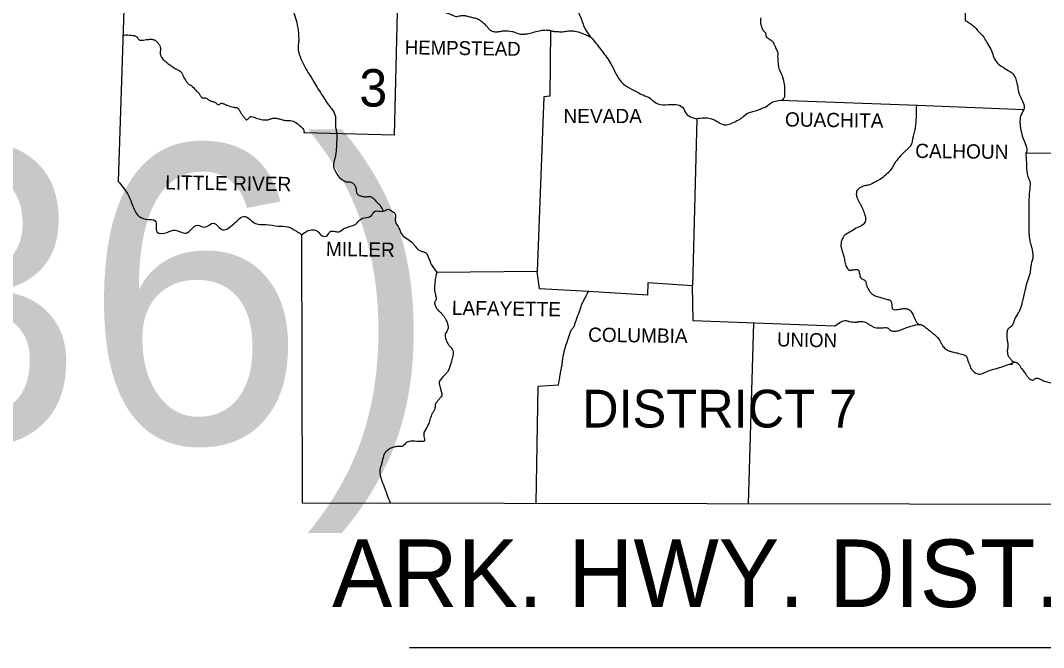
# Model space of a CAD drawing. Extents: x 0 to 3171, y 0 to 2059.
# Drawn here: x 2503.4 to 2812.1, y 1309.2 to 1498.5 of the extents above; entities that cross this region are included whole.
import ezdxf

# ---------------------------------------------------------------- set-up
doc = ezdxf.new("R2010")
doc.units = 0
doc.layers.add('Default', color=7, linetype='Continuous')
doc.layers.add('Level 1', color=7, linetype='Continuous')

msp = doc.modelspace()

# ---------------------------------------------------------------- linework, layer by layer
at = {"layer": 'Default'}
msp.add_line((2620.8, 1309.22), (2939.39, 1309.22), dxfattribs=at)
at = {"layer": 'Level 1'}
for points in [[(2521.17, 1887.43), (2541.87, 1721.24), (2532.87, 1449.94)], [(2602.57, 1557.14), (2602.57, 1543.84), (2604.77, 1543.44), (2604.57, 1531.04), (2617.77, 1530.04), (2616.17, 1463.94), (2588.97, 1464.64)], [(2803.21, 1511.94), (2788.57, 1511.04), (2788.47, 1498.54)], [(2663.37, 1495.49), (2663.17, 1475.64), (2661.37, 1475.44), (2659.37, 1422.75)], [(2732.67, 1474.44), (2774.07, 1472.94), (2806.18, 1471.69)], [(2707.47, 1468.84), (2706.17, 1418.45), (2692.67, 1419.35), (2692.57, 1415.65), (2674.78, 1416.69)], [(2806.77, 1458.44), (2851.97, 1458.54)], [(2588.17, 1433.84), (2588.37, 1352.95), (2954.87, 1352.35)], [(2659.37, 1422.75), (2629.07, 1422.45)], [(2674.78, 1416.69), (2660.07, 1417.55), (2659.37, 1422.75)], [(2749.07, 1406.25), (2706.37, 1407.85), (2706.17, 1418.45)], [(2724.58, 1407.16), (2722.99, 1352.73)], [(2665.77, 1388.45), (2659.57, 1388.05), (2658.89, 1352.83)]]:
    msp.add_lwpolyline(points, dxfattribs=at)
for points in [[(2658.07, 1536.64), (2659.67, 1535.64), (2661.57, 1534.74), (2662.57, 1533.24), (2662.97, 1530.94), (2663.67, 1528.44), (2663.87, 1525.84), (2663.27, 1524.44), (2664.07, 1521.24), (2664.37, 1519.04), (2664.67, 1516.44), (2665.47, 1512.94), (2666.77, 1510.54), (2667.97, 1507.64), (2669.97, 1504.54), (2671.67, 1501.14), (2672.47, 1499.34), (2673.97, 1495.64), (2675.87, 1493.14), (2678.87, 1489.34), (2681.57, 1485.44), (2683.07, 1482.54), (2685.37, 1479.34), (2687.97, 1477.74), (2691.27, 1476.04), (2693.37, 1475.04), (2695.77, 1473.34), (2698.87, 1473.14), (2701.17, 1473.14), (2703.27, 1472.24), (2704.27, 1470.44), (2706.07, 1469.24), (2707.47, 1468.84)], [(2581.07, 1531.04), (2581.57, 1528.04), (2581.76, 1527.38), (2582.01, 1526.74), (2582.27, 1526.1), (2582.47, 1525.44), (2582.53, 1524.95), (2582.53, 1524.44), (2582.53, 1523.94), (2582.57, 1523.44), (2582.77, 1522.69), (2583.04, 1521.95), (2583.31, 1521.21), (2583.47, 1520.44), (2583.47, 1519.34), (2583.53, 1518.79), (2583.62, 1518.24), (2583.72, 1517.69), (2583.77, 1517.14), (2583.71, 1516.84), (2583.57, 1516.54), (2583.43, 1516.24), (2583.37, 1515.94), (2583.46, 1515.35), (2583.63, 1514.75), (2583.8, 1514.15), (2583.87, 1513.54), (2583.77, 1511.74), (2583.77, 1510.24), (2583.87, 1507.74), (2584.01, 1507.18), (2584.23, 1506.63), (2584.48, 1506.1), (2584.67, 1505.54), (2585.47, 1502.24), (2585.97, 1500.54), (2586.77, 1497.94), (2587.27, 1494.74), (2587.37, 1492.34), (2587.34, 1491.79), (2587.26, 1491.24), (2587.19, 1490.69), (2587.17, 1490.14), (2587.77, 1487.64), (2588.87, 1485.14), (2590.27, 1482.74), (2591.97, 1480.04), (2593.17, 1477.94), (2594.67, 1475.64), (2595.87, 1473.74), (2596.3, 1473.13), (2596.76, 1472.55), (2597.23, 1471.96), (2597.67, 1471.34), (2598.47, 1469.34), (2598.52, 1468.64), (2598.49, 1467.94), (2598.45, 1467.24), (2598.47, 1466.54), (2598.57, 1465.89), (2598.7, 1465.25), (2598.82, 1464.6), (2598.87, 1463.94), (2598.77, 1461.04), (2598.57, 1458.44), (2598.43, 1457.54), (2598.21, 1456.64), (2598, 1455.74), (2597.87, 1454.84), (2598.37, 1453.14), (2600.27, 1450.64), (2601.47, 1449.94), (2601.98, 1449.82), (2602.53, 1449.8), (2603.07, 1449.75), (2603.57, 1449.54), (2604.16, 1448.9), (2604.57, 1448.14), (2604.72, 1447.62), (2604.76, 1447.05), (2604.86, 1446.5), (2604.98, 1446.26), (2605.17, 1446.04), (2606.19, 1445.55), (2607.27, 1445.34), (2607.56, 1445.31), (2607.87, 1445.33), (2608.49, 1445.39), (2609.08, 1445.39), (2609.57, 1445.14), (2610.67, 1443.94), (2612.17, 1442.34), (2612.9, 1440.94)], [(2617.13, 1503.54), (2621.37, 1503.14), (2624.87, 1502.74), (2626.23, 1502.64), (2626.9, 1502.57), (2627.24, 1502.51), (2627.57, 1502.44), (2628.29, 1502.23), (2628.98, 1501.98), (2630.37, 1501.44), (2632.87, 1500.54), (2633.27, 1500.38), (2633.67, 1500.19), (2634.06, 1500), (2634.47, 1499.84), (2635.13, 1499.77), (2635.81, 1499.89), (2636.5, 1500.03), (2637.17, 1500.04), (2638.32, 1499.82), (2639.47, 1499.54), (2640.8, 1499.19), (2641.45, 1498.96), (2641.76, 1498.81), (2642.07, 1498.64), (2643.07, 1497.84), (2643.97, 1496.94), (2644.26, 1496.62), (2644.52, 1496.28), (2645.17, 1495.64), (2645.73, 1495.34), (2646.31, 1495.19), (2647.47, 1495.14), (2647.94, 1495.2), (2648.42, 1495.3), (2648.89, 1495.4), (2649.37, 1495.44), (2651.67, 1495.24), (2652.33, 1495.07), (2652.97, 1494.82), (2653.61, 1494.59), (2654.27, 1494.44), (2654.79, 1494.4), (2655.32, 1494.41), (2656.37, 1494.54), (2658.07, 1494.94), (2660.07, 1495.44), (2661.32, 1495.64), (2661.95, 1495.66), (2662.57, 1495.64), (2663.05, 1495.57), (2663.52, 1495.45), (2663.99, 1495.33), (2664.47, 1495.24), (2665.72, 1495.16), (2666.97, 1495.14), (2667.7, 1495.2), (2668.42, 1495.32), (2669.15, 1495.42), (2669.51, 1495.45), (2669.87, 1495.44), (2670.61, 1495.35), (2672.79, 1494.72), (2674.21, 1494.11), (2675.6, 1493.49)], [(2726.77, 1499.34), (2726.66, 1498.4), (2726.69, 1497.92), (2726.77, 1497.44), (2726.89, 1496.98), (2727.05, 1496.52), (2727.24, 1496.08), (2727.47, 1495.64), (2727.63, 1495.43), (2727.82, 1495.23), (2728.01, 1495.05), (2728.17, 1494.84), (2728.27, 1494.53), (2728.29, 1494.17), (2728.32, 1493.83), (2728.37, 1493.67), (2728.47, 1493.54), (2728.68, 1493.37), (2728.91, 1493.23), (2729.15, 1493.1), (2729.37, 1492.94), (2729.54, 1492.81), (2729.73, 1492.67), (2730.09, 1492.4), (2730.41, 1492.1), (2730.55, 1491.93), (2730.67, 1491.74), (2730.87, 1491.32), (2731.04, 1490.9), (2731.2, 1490.47), (2731.37, 1490.04), (2731.64, 1489.5), (2731.77, 1489.23), (2731.82, 1489.09), (2731.87, 1488.94), (2731.92, 1488.6), (2731.91, 1488.25), (2731.88, 1487.89), (2731.87, 1487.54), (2731.92, 1486.84), (2731.97, 1486.14), (2732.05, 1485.29), (2732.1, 1484.87), (2732.17, 1484.44), (2732.4, 1483.67), (2732.74, 1482.93), (2733.09, 1482.2), (2733.37, 1481.44), (2733.67, 1480.24), (2733.87, 1479.24), (2733.97, 1477.54), (2733.99, 1477.04), (2734, 1476.54), (2733.99, 1476.04), (2733.98, 1475.79), (2733.97, 1475.54), (2733.88, 1475.26), (2733.69, 1474.95), (2733.15, 1474.43)], [(2788.47, 1498.54), (2790.77, 1497.04), (2792.67, 1495.04), (2794.07, 1493.54), (2794.97, 1491.84), (2796.17, 1489.84), (2797.87, 1486.04), (2799.37, 1484.74), (2801.47, 1483.44), (2802.77, 1482.54), (2804.07, 1479.64), (2804.67, 1476.74), (2805.77, 1474.14), (2806.27, 1472.14), (2805.37, 1470.14), (2805.17, 1466.14), (2805.77, 1463.44), (2806.57, 1461.44), (2807.07, 1459.14), (2806.77, 1458.44)], [(2534.33, 1494.08), (2535.34, 1494.18), (2536.38, 1494.15), (2537.35, 1494.04), (2538.17, 1493.84), (2538.53, 1493.56), (2538.87, 1493.11), (2539.23, 1492.7), (2539.67, 1492.54), (2540.57, 1492.64), (2542.17, 1492.84), (2542.54, 1492.88), (2542.92, 1492.88), (2543.3, 1492.83), (2543.67, 1492.74), (2543.99, 1492.59), (2544.27, 1492.38), (2544.53, 1492.13), (2544.77, 1491.84), (2545.07, 1491.46), (2545.34, 1491.08), (2545.54, 1490.68), (2545.67, 1490.24), (2545.69, 1489.87), (2545.64, 1489.49), (2545.58, 1489.12), (2545.57, 1488.74), (2545.67, 1488.14), (2545.79, 1487.78), (2545.94, 1487.44), (2546.37, 1486.84), (2547.57, 1485.84), (2548.87, 1484.84), (2550.07, 1484.04), (2550.33, 1483.89), (2550.61, 1483.75), (2551.18, 1483.49), (2551.7, 1483.18), (2552.07, 1482.74), (2552.27, 1482.34), (2553.07, 1480.74), (2553.51, 1480.06), (2553.78, 1479.74), (2554.07, 1479.44), (2554.36, 1479.22), (2554.68, 1479.05), (2554.99, 1478.87), (2555.27, 1478.64), (2556.57, 1477.24), (2557.17, 1476.64), (2557.43, 1476.31), (2557.65, 1475.93), (2557.88, 1475.57), (2558.02, 1475.4), (2558.17, 1475.24), (2558.42, 1475.15), (2558.71, 1475.16), (2559, 1475.19), (2559.27, 1475.14), (2559.65, 1474.93), (2560.01, 1474.69), (2560.38, 1474.44), (2560.77, 1474.24), (2561.04, 1474.16), (2561.32, 1474.09), (2561.6, 1474.02), (2561.87, 1473.94), (2562.18, 1473.77), (2562.46, 1473.54), (2562.75, 1473.31), (2563.07, 1473.14), (2563.37, 1473.17), (2563.67, 1473.35), (2563.97, 1473.52), (2564.27, 1473.54), (2564.65, 1473.4), (2565.02, 1473.24), (2565.39, 1473.08), (2565.77, 1472.94), (2567.77, 1472.34), (2568.05, 1472.3), (2568.33, 1472.29), (2568.75, 1472.22), (2568.81, 1472.18), (2568.87, 1472.14), (2569.29, 1471.73), (2569.59, 1471.25), (2569.86, 1470.74), (2570.01, 1470.48), (2570.17, 1470.24), (2570.79, 1469.42), (2571.11, 1469.02), (2571.47, 1468.64), (2571.64, 1468.56), (2571.83, 1468.62), (2572.22, 1468.97), (2572.64, 1469.39), (2572.85, 1469.52), (2573.07, 1469.54), (2573.81, 1469.35), (2574.55, 1469.08), (2575.31, 1468.81), (2576.07, 1468.64), (2577.02, 1468.55), (2577.97, 1468.54), (2578.4, 1468.64), (2578.82, 1468.8), (2579.24, 1468.96), (2579.67, 1469.04), (2580.97, 1468.94), (2581.57, 1468.81), (2582.17, 1468.64), (2582.77, 1468.47), (2583.37, 1468.34), (2583.74, 1468.32), (2584.12, 1468.34), (2584.5, 1468.37), (2584.87, 1468.34), (2586.47, 1467.74), (2587.97, 1466.54), (2588.97, 1465.24), (2588.97, 1464.64)], [(2728.17, 1472.34), (2730.77, 1474.04), (2732.67, 1474.44)], [(2773.73, 1472.96), (2773.67, 1469.85), (2773.6, 1468.3), (2773.54, 1467.52), (2773.47, 1466.74), (2773.17, 1465.19), (2772.77, 1463.64), (2772.5, 1462.23), (2772.33, 1461.52), (2772.22, 1461.18), (2772.15, 1461.01), (2772.07, 1460.84), (2771.77, 1460.38), (2771.39, 1459.99), (2770.57, 1459.24), (2769.77, 1458.45), (2768.97, 1457.64), (2767.47, 1455.84), (2767.12, 1455.31), (2766.82, 1454.74), (2766.52, 1454.18), (2766.17, 1453.64), (2764.87, 1452.24), (2763.17, 1450.84), (2761.47, 1449.84), (2759.57, 1448.94), (2759.06, 1448.78), (2758.53, 1448.68), (2758, 1448.59), (2757.47, 1448.44), (2756.64, 1448.02), (2756.28, 1447.72), (2756.12, 1447.54), (2755.97, 1447.34), (2755.7, 1446.76), (2755.62, 1446.14), (2755.87, 1444.94), (2756.28, 1444.09), (2756.72, 1443.25), (2757.17, 1442.41), (2757.57, 1441.54), (2758.17, 1439.94), (2758.3, 1439.48), (2758.39, 1439), (2758.41, 1438.52), (2758.37, 1438.04), (2757.67, 1436.94), (2756.07, 1436.04), (2754.17, 1434.94), (2752.47, 1433.94), (2752.07, 1433.62), (2751.74, 1433.21), (2751.48, 1432.75), (2751.27, 1432.24), (2751, 1431.09), (2751.07, 1429.95), (2751.25, 1429.27), (2751.47, 1428.6), (2751.68, 1427.92), (2751.87, 1427.25), (2752.02, 1426.45), (2752.17, 1425.65), (2752.55, 1424.23), (2752.91, 1423.61), (2753.16, 1423.35), (2753.3, 1423.24), (2753.47, 1423.15), (2753.72, 1423.09), (2753.97, 1423.13), (2754.22, 1423.2), (2754.47, 1423.25), (2754.69, 1423.26), (2754.92, 1423.29), (2755.37, 1423.36), (2755.82, 1423.34), (2756.05, 1423.27), (2756.16, 1423.22), (2756.27, 1423.15), (2756.42, 1422.91), (2756.47, 1422.65), (2756.57, 1422.15), (2756.97, 1420.85), (2757.27, 1420.51), (2757.71, 1420.29), (2758.17, 1420.07), (2758.47, 1419.75), (2758.54, 1419.5), (2758.57, 1419.25), (2758.61, 1418.99), (2758.67, 1418.75), (2759.05, 1417.77), (2759.57, 1416.85), (2759.89, 1416.44), (2760.24, 1416.08), (2761.07, 1415.55), (2762.17, 1415.15), (2764.47, 1414.45), (2765.67, 1414.15), (2765.84, 1414.07), (2766.15, 1413.58), (2766.31, 1412.61), (2766.47, 1411.69), (2766.66, 1411.38), (2766.97, 1411.25), (2767.77, 1411.26), (2768.57, 1411.35), (2769.77, 1411.55), (2770.78, 1411.5), (2771.28, 1411.33), (2771.53, 1411.2), (2771.77, 1411.05), (2772.31, 1410.48), (2772.67, 1409.85), (2772.91, 1409.35), (2773.12, 1408.85), (2773.33, 1408.34), (2773.57, 1407.85), (2774.1, 1407.08), (2774.38, 1406.78)], [(2728.17, 1472.34), (2727.45, 1472.05), (2726.17, 1471.54), (2724.67, 1471.04), (2723.27, 1470.64), (2721.47, 1469.44), (2720.07, 1468.44), (2718.17, 1467.54), (2716.37, 1466.94), (2714.17, 1467.64), (2712.97, 1468.34), (2711.67, 1468.84), (2707.47, 1468.84)], [(2806.77, 1458.44), (2806.85, 1456.89), (2806.94, 1455.34), (2807.17, 1452.24), (2807.35, 1451.48), (2807.65, 1450.74), (2807.95, 1450), (2808.04, 1449.63), (2808.07, 1449.24), (2808.02, 1448.45), (2807.93, 1447.65), (2807.83, 1446.85), (2807.77, 1446.04), (2807.67, 1442.94), (2807.67, 1440.14), (2807.67, 1437.44), (2807.67, 1434.64), (2807.87, 1432.64), (2808.02, 1431.91), (2808.21, 1431.19), (2808.4, 1430.47), (2808.57, 1429.75), (2808.81, 1428.39), (2808.88, 1427.72), (2808.87, 1427.05), (2808.77, 1426.39), (2808.6, 1425.74), (2808.41, 1425.1), (2808.27, 1424.45), (2808.2, 1423.85), (2808.14, 1423.24), (2808.08, 1422.64), (2807.97, 1422.05), (2807.79, 1421.44), (2807.58, 1420.84), (2807.36, 1420.25), (2807.17, 1419.65), (2806.47, 1416.95), (2805.67, 1413.45), (2805.36, 1412.28), (2805.18, 1411.71), (2804.97, 1411.15), (2804.67, 1410.52), (2804.3, 1409.93), (2803.92, 1409.34), (2803.57, 1408.75), (2803.33, 1408.21), (2803.11, 1407.65), (2802.9, 1407.09), (2802.67, 1406.55), (2802.36, 1406.17), (2801.94, 1405.87), (2801.54, 1405.56), (2801.38, 1405.37), (2801.27, 1405.15), (2801.05, 1403.95), (2801.07, 1402.75), (2801.13, 1402.2), (2801.22, 1401.65), (2801.31, 1401.1), (2801.37, 1400.55), (2801.35, 1400.05), (2801.27, 1399.55), (2801.19, 1399.05), (2801.17, 1398.55), (2801.35, 1397.58), (2801.87, 1396.65), (2802.2, 1396.24), (2802.56, 1395.85), (2803.3, 1395.35)], [(2532.87, 1449.94), (2535.77, 1446.14), (2536.97, 1443.44), (2538.67, 1439.94), (2541.17, 1438.54), (2544.07, 1438.04), (2544.67, 1434.64), (2547.67, 1434.54), (2550.07, 1435.24), (2553.37, 1434.34), (2556.87, 1436.74), (2558.87, 1436.14), (2561.77, 1437.34), (2563.97, 1435.54), (2567.77, 1437.14), (2571.17, 1439.34), (2574.37, 1437.24), (2577.47, 1436.94), (2581.17, 1436.44), (2584.07, 1436.24), (2586.67, 1434.94), (2587.98, 1434.04), (2588.17, 1433.84)], [(2588.17, 1433.84), (2591.67, 1435.34), (2593.17, 1434.84), (2594.47, 1433.54), (2595.97, 1433.54), (2596.77, 1434.74), (2598.27, 1434.84), (2599.47, 1434.74), (2600.77, 1435.54), (2601.87, 1436.04), (2603.37, 1436.54), (2604.47, 1436.94), (2605.47, 1438.04), (2607.27, 1438.94), (2609.37, 1439.64), (2609.97, 1440.64), (2610.97, 1441.04), (2612.97, 1440.94), (2614.27, 1441.54), (2615.37, 1441.04), (2616.37, 1440.34), (2616.57, 1437.74), (2617.37, 1436.34), (2618.57, 1433.84), (2620.27, 1432.54), (2621.87, 1431.24), (2622.47, 1430.44), (2624.17, 1428.95), (2625.67, 1428.45), (2626.37, 1427.35), (2627.47, 1424.75), (2629.07, 1422.45)], [(2629.07, 1422.45), (2628.72, 1421.16), (2628.58, 1420.34), (2628.47, 1419.55), (2628.37, 1417.25), (2628.44, 1416.56), (2628.6, 1415.88), (2628.77, 1415.21), (2628.87, 1414.55), (2628.8, 1414.22), (2628.61, 1413.89), (2628.43, 1413.57), (2628.37, 1413.25), (2628.46, 1412.77), (2628.63, 1412.29), (2629.17, 1411.35), (2629.54, 1410.92), (2629.93, 1410.56), (2630.31, 1410.22), (2630.67, 1409.85), (2631.25, 1409.09), (2631.77, 1408.25), (2632.04, 1407.67), (2632.24, 1407.1), (2632.38, 1406.52), (2632.47, 1405.95), (2632.36, 1405.3), (2632.02, 1404.65), (2631.68, 1404), (2631.57, 1403.35), (2631.7, 1402.67), (2631.91, 1401.99), (2632.57, 1400.65), (2632.78, 1400.37), (2633.02, 1400.15), (2633.26, 1399.92), (2633.47, 1399.65), (2633.97, 1398.05), (2633.87, 1397.27), (2633.71, 1396.5), (2633.27, 1394.95), (2632.37, 1392.65), (2632.16, 1392.32), (2631.93, 1392.03), (2631.41, 1391.48), (2630.87, 1390.94), (2630.37, 1390.35), (2629.77, 1389.25), (2630.07, 1387.75), (2630.21, 1387.14), (2630.37, 1386.54), (2630.51, 1385.94), (2630.55, 1385.64), (2630.56, 1385.49), (2630.57, 1385.35), (2630.39, 1384.98), (2630.22, 1384.81), (2630.07, 1384.65), (2629.41, 1383.8), (2628.77, 1382.95), (2628.59, 1382.51), (2628.53, 1382.02), (2628.49, 1381.51), (2628.37, 1381.05), (2628.16, 1380.64), (2627.91, 1380.25), (2627.67, 1379.86), (2627.47, 1379.45), (2627.2, 1378.73), (2626.97, 1378), (2626.73, 1377.26), (2626.47, 1376.55), (2626.18, 1375.93), (2625.84, 1375.34), (2625.49, 1374.74), (2625.17, 1374.15), (2625.11, 1373.39), (2625.27, 1372.5), (2625.33, 1371.76), (2625.22, 1371.53), (2624.97, 1371.45), (2622.97, 1371.45), (2620.67, 1371.45), (2620.09, 1371.24), (2619.6, 1370.77), (2619.12, 1370.27), (2618.57, 1369.95), (2618.11, 1369.89), (2617.63, 1369.89), (2617.14, 1369.9), (2616.67, 1369.85), (2615.49, 1369.53), (2614.37, 1368.95), (2613.89, 1368.54), (2613.49, 1368.09), (2612.97, 1367.05), (2612.47, 1364.95), (2612.32, 1364.45), (2612.15, 1363.95), (2611.87, 1362.95), (2611.82, 1362.1), (2611.94, 1361.24), (2612.18, 1360.38), (2612.47, 1359.55), (2613.37, 1357.15), (2614.07, 1355.25), (2614.97, 1352.9)], [(2665.77, 1388.45), (2666.27, 1391.65), (2666.38, 1392.27), (2666.51, 1392.9), (2666.65, 1393.52), (2666.77, 1394.15), (2666.86, 1394.74), (2666.92, 1395.35), (2666.99, 1395.95), (2667.07, 1396.55), (2667.67, 1399.25), (2668.57, 1402.15), (2669.37, 1404.55), (2669.47, 1404.78), (2669.6, 1404.99), (2669.92, 1405.4), (2670.23, 1405.8), (2670.36, 1406.02), (2670.47, 1406.25), (2670.65, 1406.74), (2670.82, 1407.25), (2670.99, 1407.75), (2671.17, 1408.25), (2672.07, 1410.65), (2672.28, 1411.28), (2672.49, 1411.91), (2672.7, 1412.54), (2672.97, 1413.15), (2674.78, 1416.69)], [(2749.07, 1406.25), (2750.67, 1407.35), (2752.17, 1407.95), (2752.92, 1407.82), (2753.29, 1407.72), (2753.67, 1407.65), (2755.27, 1407.45), (2755.62, 1407.46), (2755.97, 1407.53), (2756.32, 1407.61), (2756.67, 1407.65), (2758.47, 1407.35), (2758.87, 1407.14), (2759.24, 1406.9), (2759.59, 1406.66), (2759.97, 1406.45), (2760.8, 1405.99), (2761.67, 1405.75), (2763.37, 1405.75), (2764.87, 1405.75), (2765.23, 1405.62), (2765.53, 1405.33), (2765.83, 1405.03), (2766.17, 1404.85), (2766.76, 1404.76), (2767.37, 1404.74), (2767.98, 1404.8), (2768.57, 1404.95), (2769.07, 1405.14), (2769.57, 1405.35), (2770.07, 1405.56), (2770.57, 1405.75), (2772.57, 1406.35), (2773.24, 1406.55), (2773.94, 1406.73), (2774.62, 1406.79), (2774.95, 1406.75), (2775.27, 1406.65), (2776.52, 1405.88), (2777.67, 1404.95), (2778.53, 1404.26), (2779.37, 1403.55), (2780.77, 1401.95), (2781.04, 1401.51), (2781.27, 1401.05), (2781.5, 1400.59), (2781.77, 1400.15), (2782.87, 1399.15), (2783.31, 1398.92), (2783.75, 1398.73), (2784.67, 1398.45), (2786.07, 1398.15), (2787.77, 1397.65), (2788.25, 1397.51), (2788.48, 1397.41), (2788.67, 1397.25), (2788.95, 1396.8), (2789.14, 1396.32), (2789.29, 1395.83), (2789.47, 1395.35), (2789.61, 1395.02), (2789.72, 1394.69), (2789.95, 1394.03), (2790.26, 1393.39), (2790.49, 1393.06), (2790.62, 1392.91), (2790.77, 1392.75), (2791.37, 1392.25), (2792, 1391.92), (2792.64, 1391.78), (2793.27, 1391.85), (2794.04, 1392.11), (2794.82, 1392.44), (2795.59, 1392.77), (2796.37, 1393.05), (2798.87, 1393.75), (2800.67, 1394.35), (2801.77, 1394.75), (2802.01, 1394.79), (2802.27, 1394.8), (2802.52, 1394.8), (2802.77, 1394.85), (2802.79, 1394.86), (2802.76, 1394.88), (2802.63, 1394.94), (2802.49, 1395), (2802.46, 1395.02), (2802.47, 1395.05), (2802.75, 1395.18), (2803.07, 1395.3), (2803.67, 1395.35), (2803.96, 1395.23), (2804.26, 1395.05), (2804.77, 1394.55), (2804.96, 1394.27), (2805.12, 1393.99), (2805.29, 1393.71), (2805.47, 1393.45), (2806.67, 1391.85), (2807.19, 1391.14), (2807.47, 1390.79), (2807.77, 1390.45), (2808.01, 1390.24), (2808.3, 1390.1), (2808.59, 1390), (2808.87, 1389.95), (2809.14, 1390.03), (2809.41, 1390.27), (2809.69, 1390.49), (2809.97, 1390.55), (2811.47, 1390.05), (2812.77, 1389.55), (2814.27, 1389.15), (2814.59, 1389.11), (2814.92, 1389.09), (2815.25, 1389.08), (2815.57, 1389.05), (2817.27, 1388.65), (2818.57, 1387.95), (2819.77, 1387.25), (2820.97, 1385.95), (2822.17, 1383.95), (2822.3, 1383.56), (2822.37, 1383.16), (2822.44, 1382.75), (2822.57, 1382.35), (2823.16, 1381.45), (2823.55, 1381.08), (2823.97, 1380.75), (2824.29, 1380.69), (2824.66, 1380.78), (2825.01, 1380.86), (2825.27, 1380.75), (2825.76, 1380.1), (2826.23, 1379.46), (2827.17, 1378.15), (2827.87, 1377.15), (2828.52, 1376.18), (2828.89, 1375.74), (2829.12, 1375.53), (2829.37, 1375.35), (2829.63, 1375.26), (2829.91, 1375.29), (2830.19, 1375.34), (2830.47, 1375.35), (2832.6, 1374.94)]]:
    msp.add_spline(points, degree=3, dxfattribs=at)

# ---------------------------------------------------------------- texts
at = {"layer": 'Default'}
for s, height, p in [('FED. AID PROJ. NHPP-0044(36)', 89.9998, (843.84, 1370.9)), ('  ARK. HWY. DIST. NO. 9', 20.4, (2582.28, 1321.44))]:
    msp.add_text(s, height=height, dxfattribs=at).set_placement(p)
at = {"layer": 'Level 1'}
for s, height, rotation, p in [('HEMPSTEAD', 4.199, 359.1885, (2619.37, 1488.34)), ('OUACHITA', 4.301, 359.2043, (2734.07, 1466.54)), ('CALHOUN', 4.301, 359.3634, (2773.37, 1457.04)), ('LITTLE RIVER', 4.3006, 359.1697, (2547.07, 1447.54)), ('MILLER', 4.299, 359.132, (2595.57, 1427.45)), ('LAFAYETTE', 4.299, 359.1839, (2633.57, 1409.65)), ('COLUMBIA', 4.299, 359.2125, (2674.67, 1401.55)), ('UNION', 4.2, 358.9584, (2731.67, 1400.15))]:
    msp.add_text(s, height=height, rotation=rotation, dxfattribs=at).set_placement(p)
for s, height, p in [('3', 11.3, (2605.67, 1472.54)), ('NEVADA', 4.3, (2667.27, 1467.54)), ('DISTRICT 7', 11.4, (2672.87, 1375.65))]:
    msp.add_text(s, height=height, dxfattribs=at).set_placement(p)

doc.saveas('drawing.dxf')
